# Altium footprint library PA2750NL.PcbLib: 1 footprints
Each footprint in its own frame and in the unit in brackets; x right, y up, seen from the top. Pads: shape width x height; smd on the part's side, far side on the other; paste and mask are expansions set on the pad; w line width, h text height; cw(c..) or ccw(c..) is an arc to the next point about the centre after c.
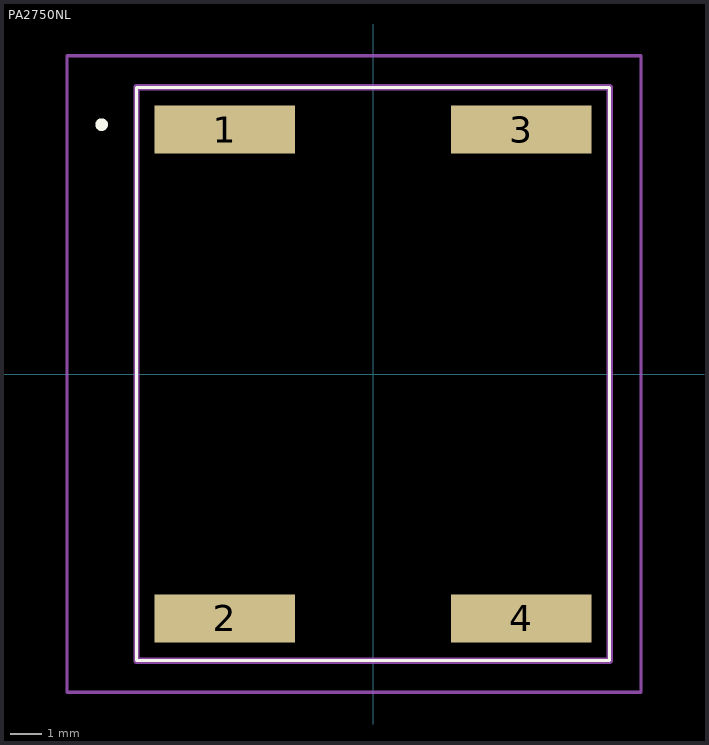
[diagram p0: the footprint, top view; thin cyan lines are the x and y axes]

## PA2750NL [mm]
pads (4):
  rect 4.45x1.52 smd: 1(-4.7,7.745) 2(-4.7,-7.745) 3(4.7,7.745) 4(4.7,-7.745)
Top Overlay:
  lines w0.1: -7.495,-9.08 7.495,-9.08 7.495,9.08 -7.495,9.08 -7.495,-9.08
  lines w0.2: -8.6,7.8 cw(c-8.6,7.9) -8.6,8 ; -8.6,7.8 -8.6,7.8 ; -8.6,7.8 ccw(c-8.6,7.9) -8.6,8 ; -8.6,8 -8.6,8
Mechanical 15:
  lines w0.2: -7.495,-9.08 7.495,-9.08 7.495,9.08 -7.495,9.08 -7.495,-9.08
Mechanical 20:
  lines w0.1: -9.7,-10.08 8.495,-10.08 8.495,10.08 -9.7,10.08 -9.7,-10.08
